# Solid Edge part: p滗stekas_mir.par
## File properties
Last saved by: Andris
Revision: 52
Accuracy: 0,990
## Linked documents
stekas.par
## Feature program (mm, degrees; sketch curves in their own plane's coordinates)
part copy "CopiedPart_1"
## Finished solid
Body 1: solid body, 109 faces, 276 edges, 184 vertices, 3 separate solids.
  Faces by surface: plane 92, swept 8, offset 4, cylinder 3, spline 2
  Edges by curve: line 229, spline 17, intersection 16, curve on surface 8, circle 6
Bounding box of the edges (mm; curved faces can reach further): 45.439 x 33.540 x 16.149, from (-19.7553, -16.7769, -3.4038) to (25.684, 16.763, 12.7453).
Cylindrical faces by radius (mm): R16.6383 x3
Planar faces by outward normal: +x 13, +y 15, +z 20, -x 8, -y 19, -z 12, oblique 5
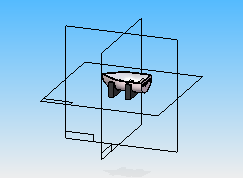
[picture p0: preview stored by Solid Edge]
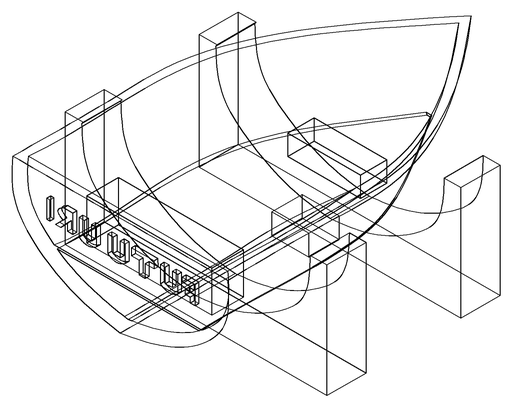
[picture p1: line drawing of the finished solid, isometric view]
